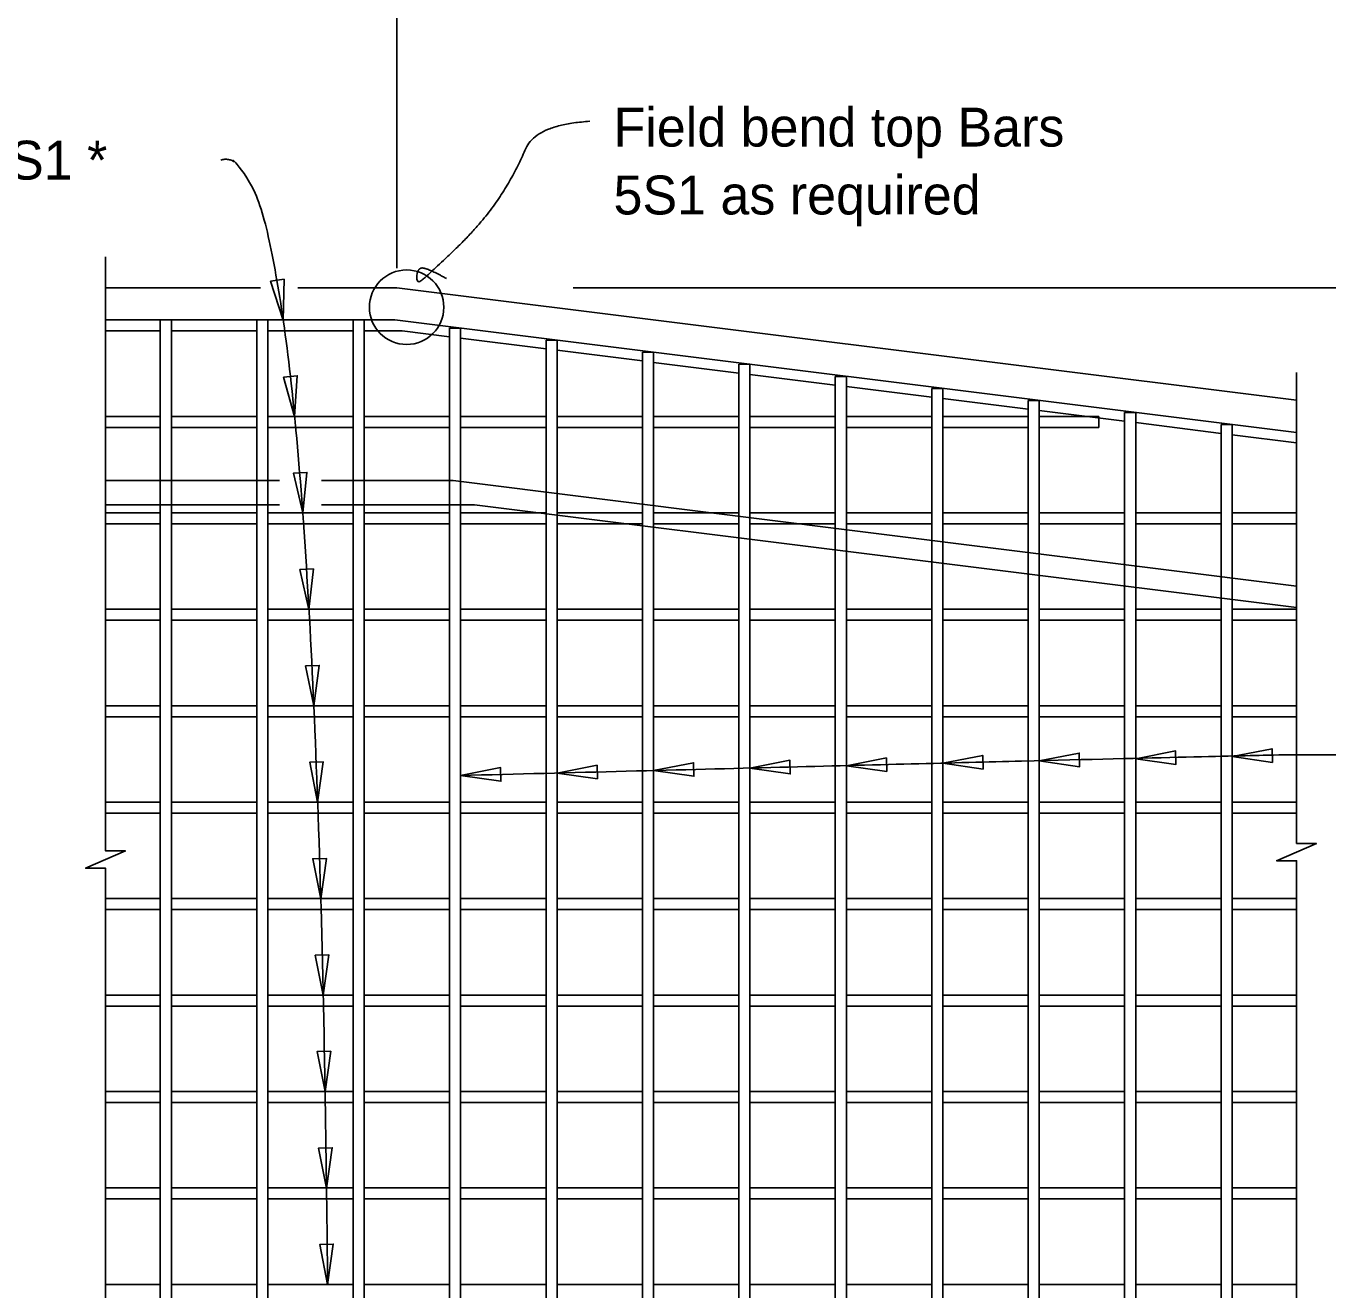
# Model space of a CAD drawing. Extents: x 120588.1 to 120659.6, y 120683.4 to 120715.5.
# Drawn here: x 120608.54 to 120615.29, y 120699.22 to 120705.78 of the extents above; entities that cross this region are included whole.
import ezdxf

# ---------------------------------------------------------------- set-up
doc = ezdxf.new("R2010")
doc.units = 0
for name, color, linetype in [('Patterning', 7, 'Continuous'), ('SheetBorder_dp', 7, 'Continuous'), ('SheetLines_dp', 7, 'Continuous'), ('SupstrConc', 7, 'Continuous')]:
    doc.layers.add(name, color=color, linetype=linetype)

msp = doc.modelspace()

# ---------------------------------------------------------------- linework, layer by layer
at = {"layer": 'SheetBorder_dp'}
for p, q in [((120609.7562, 120704.4204), (120608.952, 120704.4204)), ((120610.4626, 120704.4204), (120609.9485, 120704.4204)), ((120610.4626, 120704.4204), (120615.1275, 120703.8373)), ((120608.952, 120703.4204), (120609.8533, 120703.4204)), ((120610.0721, 120703.4204), (120610.7547, 120703.4204)), ((120610.7547, 120703.4204), (120615.1275, 120702.8738)), ((120608.952, 120703.2954), (120609.8533, 120703.2954)), ((120610.0721, 120703.2954), (120610.8658, 120703.2954)), ((120610.8658, 120703.2954), (120615.1275, 120702.7627))]:
    msp.add_line(p, q, dxfattribs=at)
at = {"layer": 'SheetLines_dp'}
for p, q in [((120610.4626, 120704.5212), (120610.4626, 120706.077)), ((120611.3758, 120704.4204), (120627.6224, 120704.4204))]:
    msp.add_line(p, q, dxfattribs=at)
for points in [[(120608.952, 120699.087), (120608.952, 120701.4106), (120608.8486, 120701.4106), (120608.952, 120701.4556), (120609.0553, 120701.5006), (120608.952, 120701.5006), (120608.952, 120704.5808)], [(120615.1274, 120701.1963), (120615.1274, 120701.4501), (120615.0241, 120701.4501), (120615.1274, 120701.4951), (120615.2308, 120701.5401), (120615.1274, 120701.5401), (120615.1274, 120703.9817)], [(120615.1275, 120697.6639), (120615.1275, 120698.7724), (120615.0241, 120698.7724), (120615.1275, 120698.8174), (120615.2308, 120698.8624), (120615.1275, 120698.8624), (120615.1275, 120701.1964)]]:
    msp.add_lwpolyline(points, dxfattribs=at)
for points in [[(120609.873, 120704.2532), (120609.8776, 120704.4644), (120609.8078, 120704.4541)], [(120609.932, 120703.7532), (120609.9456, 120703.964), (120609.8754, 120703.9567)], [(120609.9742, 120703.2532), (120609.9963, 120703.4633), (120609.9259, 120703.4588)], [(120610.0063, 120702.7532), (120610.03, 120702.9631), (120609.9596, 120702.9592)], [(120610.0315, 120702.2532), (120610.0598, 120702.4625), (120609.9892, 120702.4602)], [(120614.7933, 120701.9899), (120615.0024, 120701.96), (120615.0006, 120702.0306)], [(120610.0515, 120701.7532), (120610.0809, 120701.9624), (120610.0104, 120701.9604)], [(120611.7933, 120701.9175), (120612.0024, 120701.8876), (120612.0006, 120701.9582)], [(120612.2933, 120701.9302), (120612.5024, 120701.9003), (120612.5006, 120701.9708)], [(120612.7933, 120701.9428), (120613.0024, 120701.9129), (120613.0006, 120701.9834)], [(120613.2933, 120701.9551), (120613.5024, 120701.9253), (120613.5006, 120701.9958)], [(120613.7933, 120701.9673), (120614.0024, 120701.9374), (120614.0006, 120702.0079)], [(120614.2933, 120701.979), (120614.5024, 120701.9491), (120614.5006, 120702.0196)], [(120610.7933, 120701.8919), (120611.0024, 120701.862), (120611.0006, 120701.9326)], [(120611.2933, 120701.9048), (120611.5024, 120701.8749), (120611.5006, 120701.9454)], [(120610.0674, 120701.2532), (120610.0968, 120701.4624), (120610.0263, 120701.4604)], [(120610.0801, 120700.7532), (120610.1095, 120700.9624), (120610.039, 120700.9604)], [(120610.0901, 120700.2532), (120610.1195, 120700.4624), (120610.049, 120700.4604)], [(120610.0978, 120699.7532), (120610.1272, 120699.9624), (120610.0567, 120699.9604)], [(120610.1036, 120699.2532), (120610.133, 120699.4624), (120610.0625, 120699.4604)]]:
    msp.add_lwpolyline(points, close=True, dxfattribs=at)
msp.add_circle((120610.513, 120704.3194), 0.1931, dxfattribs=at)
for points in [[(120611.4622, 120705.2833), (120611.1816, 120705.2655), (120611.0751, 120705.0092), (120610.9028, 120704.7512), (120610.6053, 120704.4678), (120610.566, 120704.4427), (120610.566, 120704.5107), (120610.6053, 120704.5321), (120610.7197, 120704.4678)], [(120610.1039, 120699.2537), (120610.0465, 120705.2434), (120609.5504, 120705.0822)], [(120615.4491, 120701.9991), (120615.217, 120701.9991), (120614.9491, 120701.9991), (120610.7933, 120701.8919)]]:
    msp.add_open_spline(points, degree=2, dxfattribs=at)
at = {"layer": 'SupstrConc'}
for p, q in [((120610.452, 120704.2537), (120608.952, 120704.2537)), ((120610.452, 120704.2537), (120615.1275, 120703.6693)), ((120609.236, 120704.1964), (120608.952, 120704.1964)), ((120609.736, 120704.1964), (120609.2933, 120704.1964)), ((120610.236, 120704.1964), (120609.7933, 120704.1964)), ((120610.4904, 120704.1964), (120610.2933, 120704.1964)), ((120610.4904, 120704.1964), (120610.736, 120704.1657)), ((120610.7933, 120704.1585), (120611.236, 120704.1032)), ((120611.2933, 120704.096), (120611.736, 120704.0407)), ((120611.7933, 120704.0335), (120612.236, 120703.9782)), ((120612.2933, 120703.971), (120612.736, 120703.9157)), ((120612.7933, 120703.9085), (120613.236, 120703.8532)), ((120613.2933, 120703.846), (120613.736, 120703.7907)), ((120613.7933, 120703.7835), (120614.236, 120703.7282)), ((120609.236, 120703.7537), (120608.952, 120703.7537)), ((120609.736, 120703.7537), (120609.2933, 120703.7537)), ((120610.236, 120703.7537), (120609.7933, 120703.7537)), ((120610.736, 120703.7537), (120610.2933, 120703.7537)), ((120611.236, 120703.7537), (120610.7933, 120703.7537)), ((120611.736, 120703.7537), (120611.2933, 120703.7537)), ((120612.236, 120703.7537), (120611.7933, 120703.7537)), ((120612.736, 120703.7537), (120612.2933, 120703.7537)), ((120613.236, 120703.7537), (120612.7933, 120703.7537)), ((120613.736, 120703.7537), (120613.2933, 120703.7537)), ((120614.1021, 120703.7537), (120613.7933, 120703.7537)), ((120614.1021, 120703.7537), (120614.1021, 120703.6964)), ((120614.2933, 120703.721), (120614.736, 120703.6657)), ((120609.236, 120703.6964), (120608.952, 120703.6964)), ((120609.736, 120703.6964), (120609.2933, 120703.6964)), ((120610.236, 120703.6964), (120609.7933, 120703.6964)), ((120610.736, 120703.6964), (120610.2933, 120703.6964)), ((120611.236, 120703.6964), (120610.7933, 120703.6964)), ((120611.736, 120703.6964), (120611.2933, 120703.6964)), ((120612.236, 120703.6964), (120611.7933, 120703.6964)), ((120612.736, 120703.6964), (120612.2933, 120703.6964)), ((120613.236, 120703.6964), (120612.7933, 120703.6964)), ((120613.736, 120703.6964), (120613.2933, 120703.6964)), ((120614.1021, 120703.6964), (120613.7933, 120703.6964)), ((120614.7933, 120703.6585), (120615.1275, 120703.6168)), ((120609.236, 120703.2537), (120608.952, 120703.2537)), ((120609.736, 120703.2537), (120609.2933, 120703.2537)), ((120610.236, 120703.2537), (120609.7933, 120703.2537)), ((120610.736, 120703.2537), (120610.2933, 120703.2537)), ((120611.236, 120703.2537), (120610.7933, 120703.2537)), ((120611.736, 120703.2537), (120611.2933, 120703.2537)), ((120612.236, 120703.2537), (120611.7933, 120703.2537)), ((120612.736, 120703.2537), (120612.2933, 120703.2537)), ((120613.236, 120703.2537), (120612.7933, 120703.2537)), ((120613.736, 120703.2537), (120613.2933, 120703.2537)), ((120614.236, 120703.2537), (120613.7933, 120703.2537)), ((120614.736, 120703.2537), (120614.2933, 120703.2537)), ((120615.1275, 120703.2537), (120614.7933, 120703.2537)), ((120609.236, 120703.1964), (120608.952, 120703.1964)), ((120609.736, 120703.1964), (120609.2933, 120703.1964)), ((120610.236, 120703.1964), (120609.7933, 120703.1964)), ((120610.736, 120703.1964), (120610.2933, 120703.1964)), ((120611.236, 120703.1964), (120610.7933, 120703.1964)), ((120611.736, 120703.1964), (120611.2933, 120703.1964)), ((120612.236, 120703.1964), (120611.7933, 120703.1964)), ((120612.736, 120703.1964), (120612.2933, 120703.1964)), ((120613.236, 120703.1964), (120612.7933, 120703.1964)), ((120613.736, 120703.1964), (120613.2933, 120703.1964)), ((120614.236, 120703.1964), (120613.7933, 120703.1964)), ((120614.736, 120703.1964), (120614.2933, 120703.1964)), ((120615.1275, 120703.1964), (120614.7933, 120703.1964)), ((120609.236, 120702.7537), (120608.952, 120702.7537)), ((120609.236, 120702.6964), (120608.952, 120702.6964)), ((120609.736, 120702.7537), (120609.2933, 120702.7537)), ((120609.736, 120702.6964), (120609.2933, 120702.6964)), ((120610.236, 120702.7537), (120609.7933, 120702.7537)), ((120610.236, 120702.6964), (120609.7933, 120702.6964)), ((120610.736, 120702.7537), (120610.2933, 120702.7537)), ((120610.736, 120702.6964), (120610.2933, 120702.6964)), ((120611.236, 120702.7537), (120610.7933, 120702.7537)), ((120611.236, 120702.6964), (120610.7933, 120702.6964)), ((120611.736, 120702.7537), (120611.2933, 120702.7537)), ((120611.736, 120702.6964), (120611.2933, 120702.6964)), ((120612.236, 120702.7537), (120611.7933, 120702.7537)), ((120612.236, 120702.6964), (120611.7933, 120702.6964)), ((120612.736, 120702.7537), (120612.2933, 120702.7537)), ((120612.736, 120702.6964), (120612.2933, 120702.6964)), ((120613.236, 120702.7537), (120612.7933, 120702.7537)), ((120613.236, 120702.6964), (120612.7933, 120702.6964)), ((120613.736, 120702.7537), (120613.2933, 120702.7537)), ((120613.736, 120702.6964), (120613.2933, 120702.6964)), ((120614.236, 120702.7537), (120613.7933, 120702.7537)), ((120614.236, 120702.6964), (120613.7933, 120702.6964)), ((120614.736, 120702.7537), (120614.2933, 120702.7537)), ((120614.736, 120702.6964), (120614.2933, 120702.6964)), ((120615.1275, 120702.7537), (120614.7933, 120702.7537)), ((120615.1275, 120702.6964), (120614.7933, 120702.6964)), ((120609.236, 120702.2537), (120608.952, 120702.2537)), ((120609.736, 120702.2537), (120609.2933, 120702.2537)), ((120610.236, 120702.2537), (120609.7933, 120702.2537)), ((120610.736, 120702.2537), (120610.2933, 120702.2537)), ((120611.236, 120702.2537), (120610.7933, 120702.2537)), ((120611.736, 120702.2537), (120611.2933, 120702.2537)), ((120612.236, 120702.2537), (120611.7933, 120702.2537)), ((120612.736, 120702.2537), (120612.2933, 120702.2537)), ((120613.236, 120702.2537), (120612.7933, 120702.2537)), ((120613.736, 120702.2537), (120613.2933, 120702.2537)), ((120614.236, 120702.2537), (120613.7933, 120702.2537)), ((120614.736, 120702.2537), (120614.2933, 120702.2537)), ((120615.1275, 120702.2537), (120614.7933, 120702.2537)), ((120609.236, 120702.1964), (120608.952, 120702.1964)), ((120609.736, 120702.1964), (120609.2933, 120702.1964)), ((120610.236, 120702.1964), (120609.7933, 120702.1964)), ((120610.736, 120702.1964), (120610.2933, 120702.1964)), ((120611.236, 120702.1964), (120610.7933, 120702.1964)), ((120611.736, 120702.1964), (120611.2933, 120702.1964)), ((120612.236, 120702.1964), (120611.7933, 120702.1964)), ((120612.736, 120702.1964), (120612.2933, 120702.1964)), ((120613.236, 120702.1964), (120612.7933, 120702.1964)), ((120613.736, 120702.1964), (120613.2933, 120702.1964)), ((120614.236, 120702.1964), (120613.7933, 120702.1964)), ((120614.736, 120702.1964), (120614.2933, 120702.1964)), ((120615.1275, 120702.1964), (120614.7933, 120702.1964)), ((120609.236, 120701.7537), (120608.952, 120701.7537)), ((120609.736, 120701.7537), (120609.2933, 120701.7537)), ((120610.236, 120701.7537), (120609.7933, 120701.7537)), ((120610.736, 120701.7537), (120610.2933, 120701.7537)), ((120611.236, 120701.7537), (120610.7933, 120701.7537)), ((120611.736, 120701.7537), (120611.2933, 120701.7537)), ((120612.236, 120701.7537), (120611.7933, 120701.7537)), ((120612.736, 120701.7537), (120612.2933, 120701.7537)), ((120613.236, 120701.7537), (120612.7933, 120701.7537)), ((120613.736, 120701.7537), (120613.2933, 120701.7537)), ((120614.236, 120701.7537), (120613.7933, 120701.7537)), ((120614.736, 120701.7537), (120614.2933, 120701.7537)), ((120615.1275, 120701.7537), (120614.7933, 120701.7537)), ((120609.236, 120701.6964), (120608.952, 120701.6964)), ((120609.736, 120701.6964), (120609.2933, 120701.6964)), ((120610.236, 120701.6964), (120609.7933, 120701.6964)), ((120610.736, 120701.6964), (120610.2933, 120701.6964)), ((120611.236, 120701.6964), (120610.7933, 120701.6964)), ((120611.736, 120701.6964), (120611.2933, 120701.6964)), ((120612.236, 120701.6964), (120611.7933, 120701.6964)), ((120612.736, 120701.6964), (120612.2933, 120701.6964)), ((120613.236, 120701.6964), (120612.7933, 120701.6964)), ((120613.736, 120701.6964), (120613.2933, 120701.6964)), ((120614.236, 120701.6964), (120613.7933, 120701.6964)), ((120614.736, 120701.6964), (120614.2933, 120701.6964)), ((120615.1275, 120701.6964), (120614.7933, 120701.6964)), ((120609.236, 120701.2537), (120608.952, 120701.2537)), ((120609.736, 120701.2537), (120609.2933, 120701.2537)), ((120610.236, 120701.2537), (120609.7933, 120701.2537)), ((120610.736, 120701.2537), (120610.2933, 120701.2537)), ((120611.236, 120701.2537), (120610.7933, 120701.2537)), ((120611.736, 120701.2537), (120611.2933, 120701.2537)), ((120612.236, 120701.2537), (120611.7933, 120701.2537)), ((120612.736, 120701.2537), (120612.2933, 120701.2537)), ((120613.236, 120701.2537), (120612.7933, 120701.2537)), ((120613.736, 120701.2537), (120613.2933, 120701.2537)), ((120614.236, 120701.2537), (120613.7933, 120701.2537)), ((120614.736, 120701.2537), (120614.2933, 120701.2537)), ((120615.1275, 120701.2537), (120614.7933, 120701.2537)), ((120609.236, 120701.1964), (120608.952, 120701.1964)), ((120609.736, 120701.1964), (120609.2933, 120701.1964)), ((120610.236, 120701.1964), (120609.7933, 120701.1964)), ((120610.736, 120701.1964), (120610.2933, 120701.1964)), ((120611.236, 120701.1964), (120610.7933, 120701.1964)), ((120611.736, 120701.1964), (120611.2933, 120701.1964)), ((120612.236, 120701.1964), (120611.7933, 120701.1964)), ((120612.736, 120701.1964), (120612.2933, 120701.1964)), ((120613.236, 120701.1964), (120612.7933, 120701.1964)), ((120613.736, 120701.1964), (120613.2933, 120701.1964)), ((120614.236, 120701.1964), (120613.7933, 120701.1964)), ((120614.736, 120701.1964), (120614.2933, 120701.1964)), ((120615.1275, 120701.1964), (120614.7933, 120701.1964)), ((120609.236, 120700.7537), (120608.952, 120700.7537)), ((120609.736, 120700.7537), (120609.2933, 120700.7537)), ((120610.236, 120700.7537), (120609.7933, 120700.7537)), ((120610.736, 120700.7537), (120610.2933, 120700.7537)), ((120611.236, 120700.7537), (120610.7933, 120700.7537)), ((120611.736, 120700.7537), (120611.2933, 120700.7537)), ((120612.236, 120700.7537), (120611.7933, 120700.7537)), ((120612.736, 120700.7537), (120612.2933, 120700.7537)), ((120613.236, 120700.7537), (120612.7933, 120700.7537)), ((120613.736, 120700.7537), (120613.2933, 120700.7537)), ((120614.236, 120700.7537), (120613.7933, 120700.7537)), ((120614.736, 120700.7537), (120614.2933, 120700.7537)), ((120615.1275, 120700.7537), (120614.7933, 120700.7537)), ((120609.236, 120700.6964), (120608.952, 120700.6964)), ((120609.736, 120700.6964), (120609.2933, 120700.6964)), ((120610.236, 120700.6964), (120609.7933, 120700.6964)), ((120610.736, 120700.6964), (120610.2933, 120700.6964)), ((120611.236, 120700.6964), (120610.7933, 120700.6964)), ((120611.736, 120700.6964), (120611.2933, 120700.6964)), ((120612.236, 120700.6964), (120611.7933, 120700.6964)), ((120612.736, 120700.6964), (120612.2933, 120700.6964)), ((120613.236, 120700.6964), (120612.7933, 120700.6964)), ((120613.736, 120700.6964), (120613.2933, 120700.6964)), ((120614.236, 120700.6964), (120613.7933, 120700.6964)), ((120614.736, 120700.6964), (120614.2933, 120700.6964)), ((120615.1275, 120700.6964), (120614.7933, 120700.6964)), ((120609.236, 120700.2537), (120608.952, 120700.2537)), ((120609.736, 120700.2537), (120609.2933, 120700.2537)), ((120610.236, 120700.2537), (120609.7933, 120700.2537)), ((120610.736, 120700.2537), (120610.2933, 120700.2537)), ((120611.236, 120700.2537), (120610.7933, 120700.2537)), ((120611.736, 120700.2537), (120611.2933, 120700.2537)), ((120612.236, 120700.2537), (120611.7933, 120700.2537)), ((120612.736, 120700.2537), (120612.2933, 120700.2537)), ((120613.236, 120700.2537), (120612.7933, 120700.2537)), ((120613.736, 120700.2537), (120613.2933, 120700.2537)), ((120614.236, 120700.2537), (120613.7933, 120700.2537)), ((120614.736, 120700.2537), (120614.2933, 120700.2537)), ((120615.1275, 120700.2537), (120614.7933, 120700.2537)), ((120609.236, 120700.1964), (120608.952, 120700.1964)), ((120609.736, 120700.1964), (120609.2933, 120700.1964)), ((120610.236, 120700.1964), (120609.7933, 120700.1964)), ((120610.736, 120700.1964), (120610.2933, 120700.1964)), ((120611.236, 120700.1964), (120610.7933, 120700.1964)), ((120611.736, 120700.1964), (120611.2933, 120700.1964)), ((120612.236, 120700.1964), (120611.7933, 120700.1964)), ((120612.736, 120700.1964), (120612.2933, 120700.1964)), ((120613.236, 120700.1964), (120612.7933, 120700.1964)), ((120613.736, 120700.1964), (120613.2933, 120700.1964)), ((120614.236, 120700.1964), (120613.7933, 120700.1964)), ((120614.736, 120700.1964), (120614.2933, 120700.1964)), ((120615.1275, 120700.1964), (120614.7933, 120700.1964)), ((120609.236, 120699.7537), (120608.952, 120699.7537)), ((120609.736, 120699.7537), (120609.2933, 120699.7537)), ((120610.236, 120699.7537), (120609.7933, 120699.7537)), ((120610.736, 120699.7537), (120610.2933, 120699.7537)), ((120611.236, 120699.7537), (120610.7933, 120699.7537)), ((120611.736, 120699.7537), (120611.2933, 120699.7537)), ((120612.236, 120699.7537), (120611.7933, 120699.7537)), ((120612.736, 120699.7537), (120612.2933, 120699.7537)), ((120613.236, 120699.7537), (120612.7933, 120699.7537)), ((120613.736, 120699.7537), (120613.2933, 120699.7537)), ((120614.236, 120699.7537), (120613.7933, 120699.7537)), ((120614.236, 120699.7537), (120614.1385, 120699.7537)), ((120614.736, 120699.7537), (120614.2933, 120699.7537)), ((120615.1275, 120699.7537), (120614.7933, 120699.7537)), ((120615.1275, 120699.7537), (120614.8382, 120699.7537)), ((120609.236, 120699.6964), (120608.952, 120699.6964)), ((120609.736, 120699.6964), (120609.2933, 120699.6964)), ((120610.236, 120699.6964), (120609.7933, 120699.6964)), ((120610.736, 120699.6964), (120610.2933, 120699.6964)), ((120611.236, 120699.6964), (120610.7933, 120699.6964)), ((120611.736, 120699.6964), (120611.2933, 120699.6964)), ((120612.236, 120699.6964), (120611.7933, 120699.6964)), ((120612.736, 120699.6964), (120612.2933, 120699.6964)), ((120613.236, 120699.6964), (120612.7933, 120699.6964)), ((120613.736, 120699.6964), (120613.2933, 120699.6964)), ((120614.236, 120699.6964), (120613.7933, 120699.6964)), ((120614.236, 120699.6964), (120614.1385, 120699.6964)), ((120614.736, 120699.6964), (120614.2933, 120699.6964)), ((120615.1275, 120699.6964), (120614.7933, 120699.6964)), ((120615.1275, 120699.6964), (120614.8382, 120699.6964)), ((120609.236, 120699.2537), (120608.952, 120699.2537)), ((120609.736, 120699.2537), (120609.2933, 120699.2537)), ((120610.236, 120699.2537), (120609.7933, 120699.2537)), ((120610.736, 120699.2537), (120610.2933, 120699.2537)), ((120611.236, 120699.2537), (120610.7933, 120699.2537)), ((120611.736, 120699.2537), (120611.2933, 120699.2537)), ((120612.236, 120699.2537), (120611.7933, 120699.2537)), ((120612.736, 120699.2537), (120612.2933, 120699.2537)), ((120613.236, 120699.2537), (120612.7933, 120699.2537)), ((120613.736, 120699.2537), (120613.2933, 120699.2537)), ((120614.236, 120699.2537), (120613.7933, 120699.2537)), ((120614.736, 120699.2537), (120614.2933, 120699.2537)), ((120615.1275, 120699.2537), (120614.7933, 120699.2537)), ((120615.1275, 120699.2537), (120614.8382, 120699.2537))]:
    msp.add_line(p, q, dxfattribs=at)
for points in [[(120609.236, 120704.2537), (120609.2933, 120704.2537), (120609.2933, 120696.587), (120609.236, 120696.587)], [(120609.736, 120704.2537), (120609.7933, 120704.2537), (120609.7933, 120696.587), (120609.736, 120696.587)], [(120610.236, 120704.2537), (120610.2933, 120704.2537), (120610.2933, 120696.587), (120610.236, 120696.587)], [(120610.736, 120704.211), (120610.7933, 120704.211), (120610.7933, 120696.587), (120610.736, 120696.587)], [(120611.236, 120704.1485), (120611.2933, 120704.1485), (120611.2933, 120696.587), (120611.236, 120696.587)], [(120611.736, 120704.086), (120611.7933, 120704.086), (120611.7933, 120696.587), (120611.736, 120696.587)], [(120612.236, 120704.0235), (120612.2933, 120704.0235), (120612.2933, 120696.587), (120612.236, 120696.587)], [(120612.736, 120703.961), (120612.7933, 120703.961), (120612.7933, 120696.587), (120612.736, 120696.587)], [(120613.236, 120703.8985), (120613.2933, 120703.8985), (120613.2933, 120696.587), (120613.236, 120696.587)], [(120613.736, 120703.836), (120613.7933, 120703.836), (120613.7933, 120696.587), (120613.736, 120696.587)], [(120614.236, 120703.7735), (120614.2933, 120703.7735), (120614.2933, 120696.587), (120614.236, 120696.587)], [(120614.736, 120703.711), (120614.7933, 120703.711), (120614.7933, 120696.587), (120614.736, 120696.587)]]:
    msp.add_lwpolyline(points, close=True, dxfattribs=at)

# ---------------------------------------------------------------- texts
at = {"layer": 'Patterning'}
msp.add_text('Bars 5S1 *', height=0.2016, dxfattribs=at).set_placement((120607.6725, 120704.9811))
at = {"layer": 'SheetLines_dp'}
for s, p in [('Field bend top Bars ', (120611.5859, 120705.1524)), ('5S1 as required', (120611.5859, 120704.8004))]:
    msp.add_text(s, height=0.2016, dxfattribs=at).set_placement(p)

doc.saveas('drawing.dxf')
